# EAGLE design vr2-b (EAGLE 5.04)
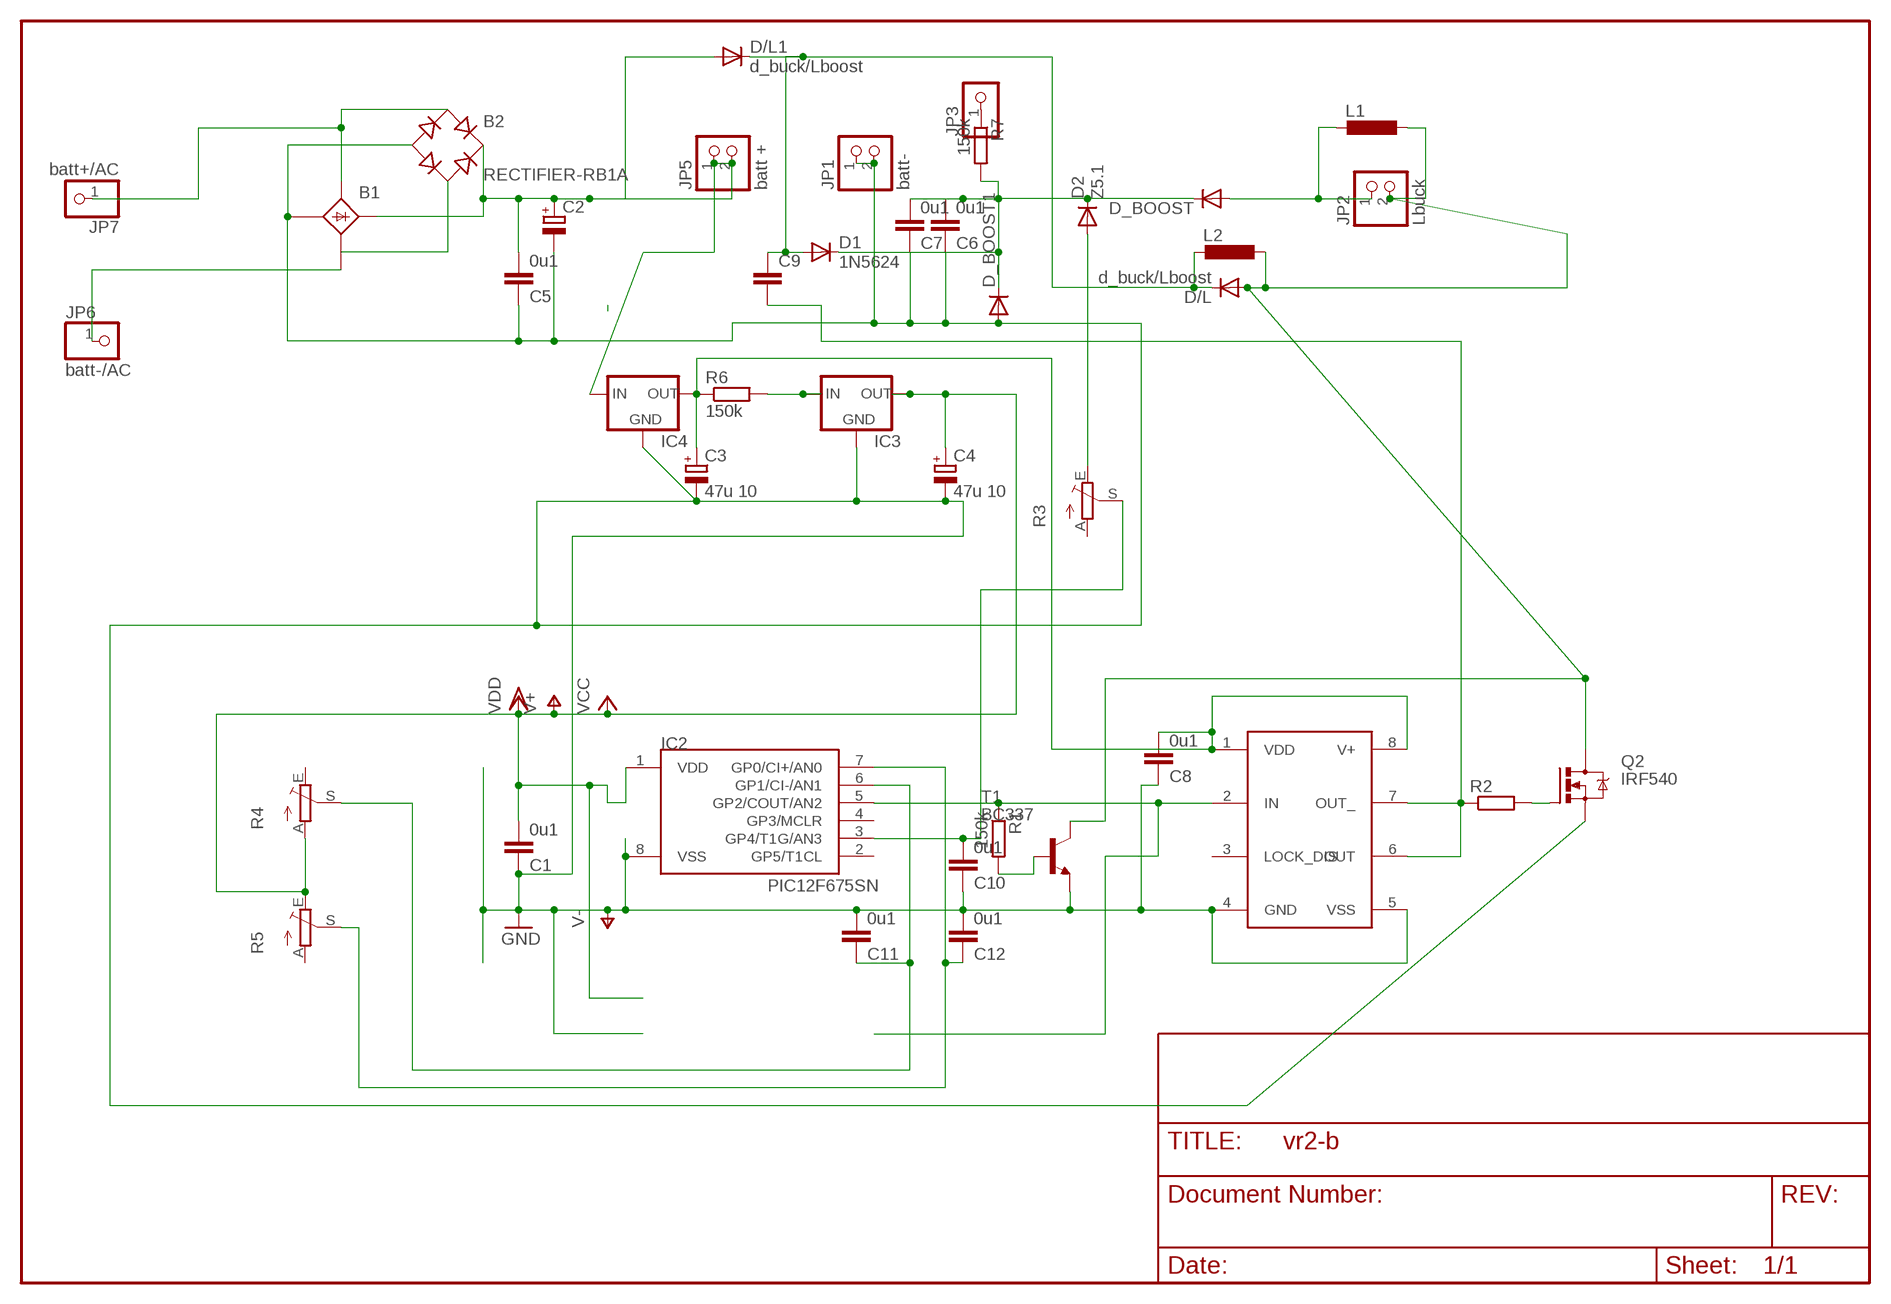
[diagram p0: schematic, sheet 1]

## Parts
B1  B25A-  [B25A-]
B2  RECTIFIER-RB1A  [RB1A]
C1  0u1  C-EUC1206  [C1206]
C2  CPOL-EUE7.5-18  [E7,5-18]
C3  47u 10  CPOL-EUE2,5-6E  [E2,5-6E]
C4  47u 10  CPOL-EUE2.5-6  [E2,5-6]
C5  0u1  C-EUC1206  [C1206]
C6  0u1  C-EUC1206  [C1206]
C7  0u1  C-EUC1206  [C1206]
C8  0u1  C-EUC1206  [C1206]
C9  C-EU050-024X044  [C050-024X044]
C10  0u1  C-EUC1206  [C1206]
C11  0u1  C-EUC1206  [C1206]
C12  0u1  C-EUC1206  [C1206]
D1  1N5624  [DO201-15]
D2  Z5.1  DIODE-D-2.5  [D-2.5]
D/L  d_buck/Lboost  DIODE-C1702-05  [C1702-05]
D/L1  d_buck/Lboost  DIODE-DO201-15  [DO201-15]
D_BOOST  DIODE-DO201-15  [DO201-15]
D_BOOST1  DIODE-DO201-15  [DO201-15]
IC1  TC4432X  [SO-08]
IC2  PIC12F675SN  [SO-08]
IC3  78LXX  [78LXX]
IC4  78LXX  [78LXX]
JP1  batt-  PINHD-1X2  [1X02]
JP2  Lbuck  PINHD-1X2  [1X02]
JP3  PINHD-1X1  [1X01]
JP5  batt +  PINHD-1X2  [1X02]
JP6  batt-/AC  PINHD-1X1  [1X01]
JP7  batt+/AC  PINHD-1X1  [1X01]
L1  DO3316P  [DO3316P]
L2  DO3316P  [DO3316P]
Q2  IRF540  [TO220BV]
R1  150k  R-EU_0207/12  [0207/12]
R2  R-EU_R1206  [R1206]
R3  TRIM_EU-CA6V  [CA6V]
R4  TRIM_EU-CA6V  [CA6V]
R5  TRIM_EU-CA6V  [CA6V]
R6  150k  R-EU_0204/7  [0204/7]
R7  150k  R-EU_0207/12  [0207/12]
T1  BC337  [TO92]

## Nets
LOAD: C6.2 C7.2 D1.C D2.C D_BOOST1.C D_BOOST.C R7.2
N$1: B1.+ B2.+ C2.+ C5.2 D/L1.A IC4.IN JP5.1 JP5.2
N$2: C9.1 D1.A D/L1.C D/L.C L2.1
N$3: B1.AC2-(AC2) JP6.1
N$4: C3.+ C8.2 IC1.1(VDD) IC1.8(V+) IC4.OUT R6.1
N$5: D_BOOST.A JP2.1 L1.1
N$6: R1.2 T1.2(B)
N$7: C9.2 IC1.6(OUT) IC1.7(OUT_) R2.1
N$8: B1.AC1 B2.AC1 JP7.1
N$9: D/L.A JP2.2 L1.2 L2.2 Q2.D T1.3(C)
N$11: B1.AC2 B2.AC2
N$12: C10.2 IC2.3(GP4/T1G/AN3) R3.S
N$13: C12.1 IC2.7(GP0/CI+/AN0) R5.S
N$14: IC1.2(IN) IC2.5(GP2/COUT/AN2) R1.1
N$15: C11.1 IC2.6(GP1/CI-/AN1) R4.S
N$16: D2.A R3.E
N$17: Q2.G R2.2
N$19: JP3.1 R7.1
N$20: IC3.IN R6.2
V+: C1.2 C4.+ IC2.1(VDD) IC3.OUT R4.A R5.E ; supply symbol labelled VCC, VDD
V-: B1.-1(-) B2.- C1.1 C2.- C3.- C4.- C5.1 C6.1 C7.1 C8.1 C10.1 C11.2 C12.2 D_BOOST1.A IC1.4(GND) IC1.5(VSS) IC2.8(VSS) IC3.GND IC4.GND JP1.1 JP1.2 Q2.S T1.1(E) ; supply symbol labelled GND
Unconnected: B1.+1(+) B1.- B1.AC1-(AC1) IC1.3(LOCK_DIS) IC2.2(GP5/T1CL) IC2.4(GP3/MCLR) R3.A R4.E R5.A

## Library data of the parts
B1 = rectifier:B25A-: RECTIFIER 25-A bridge
B2 = rectifier:RECTIFIER-: Rectifier
C1 C5-C8 C10-C12 = rcl:C-EU: CAPACITOR, European symbol
C2-C4 = rcl:CPOL-EU: POLARIZED CAPACITOR, European symbol
C9 = rcl-2:C-EU: CAPACITOR, European symbol
D1 = diode-1:1N5624: DIODE
D2 D/L D/L1 D_BOOST D_BOOST1 = diode:DIODE-: DIODE
IC1 = microchip:TC4432
IC2 = microchip-3:PIC12F6*: uPC nW 1k Program Flash memory 2x Timer Comparator 10b A/D converter/ 4xIN
IC3 IC4 = v-reg:78LXX: VOLTAGE REGULATOR
JP1 JP2 JP5 = pinhead:PINHD-1X2: PIN HEADER
JP3 JP6 JP7 = pinhead:PINHD-1X1: PIN HEADER
L1 L2 = inductor-coilcraft:DO3316P: COILCRAFT
Q2 = transistor-power:IRF540: HEXFET Power MOSFET
R1 R6 R7 = rcl:R-EU_: RESISTOR, European symbol
R2 = rcl-2:R-EU_: RESISTOR, European symbol
R3-R5 = pot:TRIM_EU-: POTENTIOMETER
T1 = transistor-neu-to92:BC337: NPN TRANSISTOR

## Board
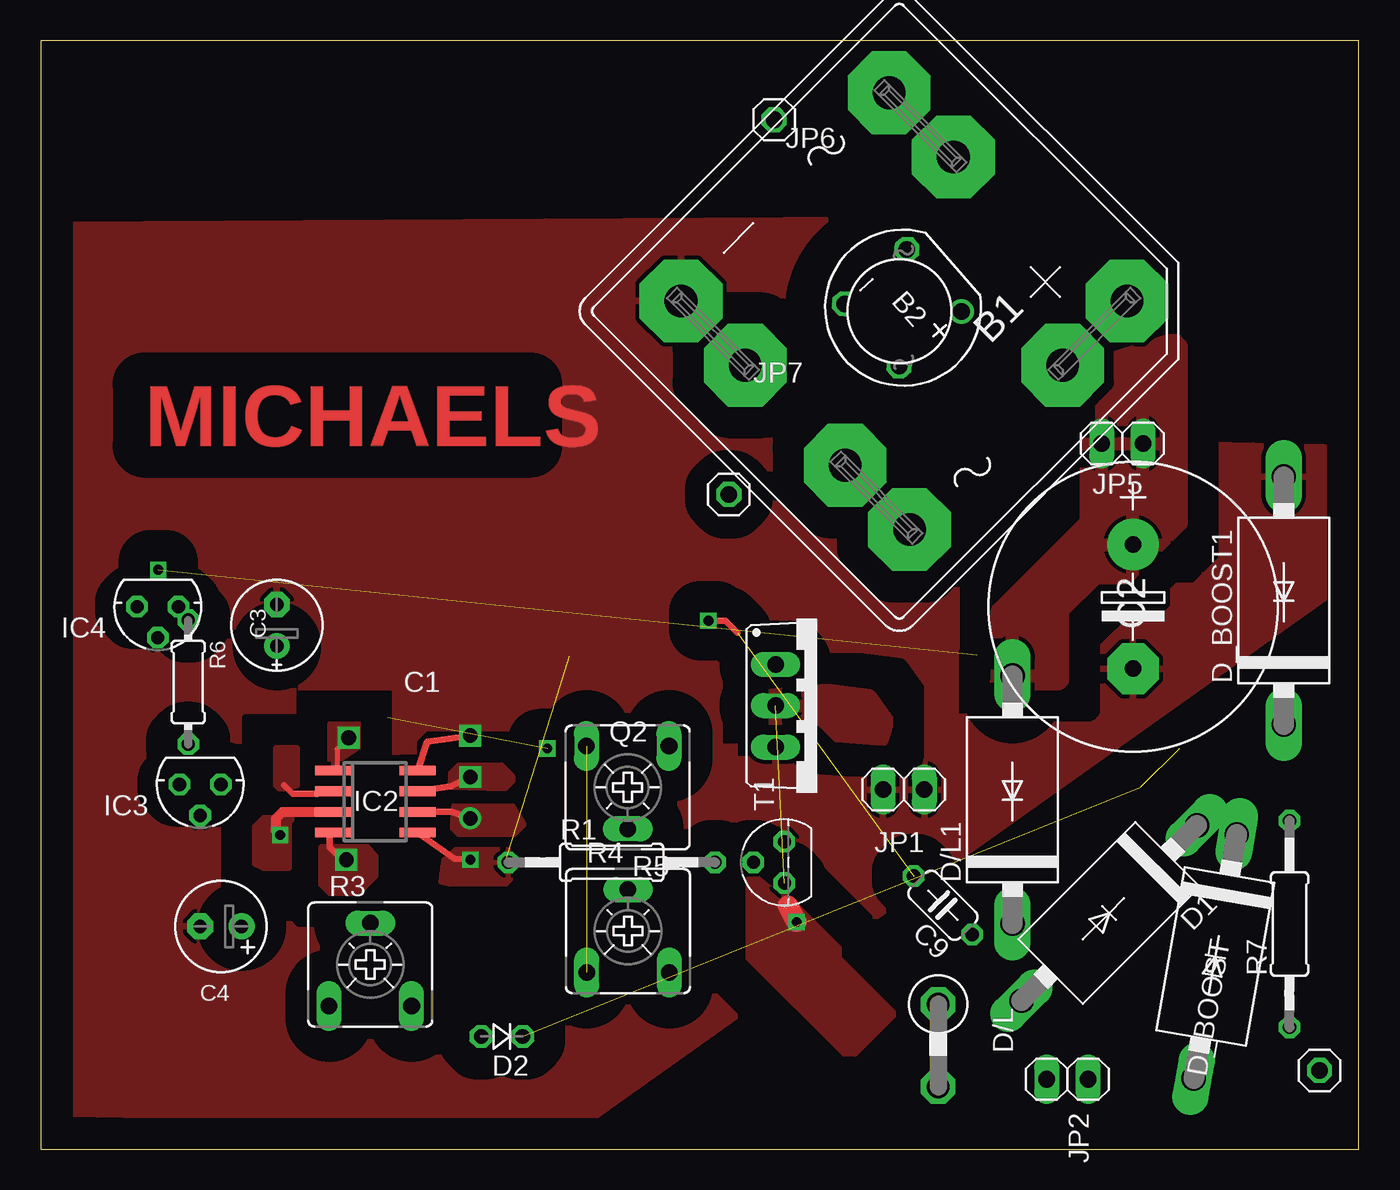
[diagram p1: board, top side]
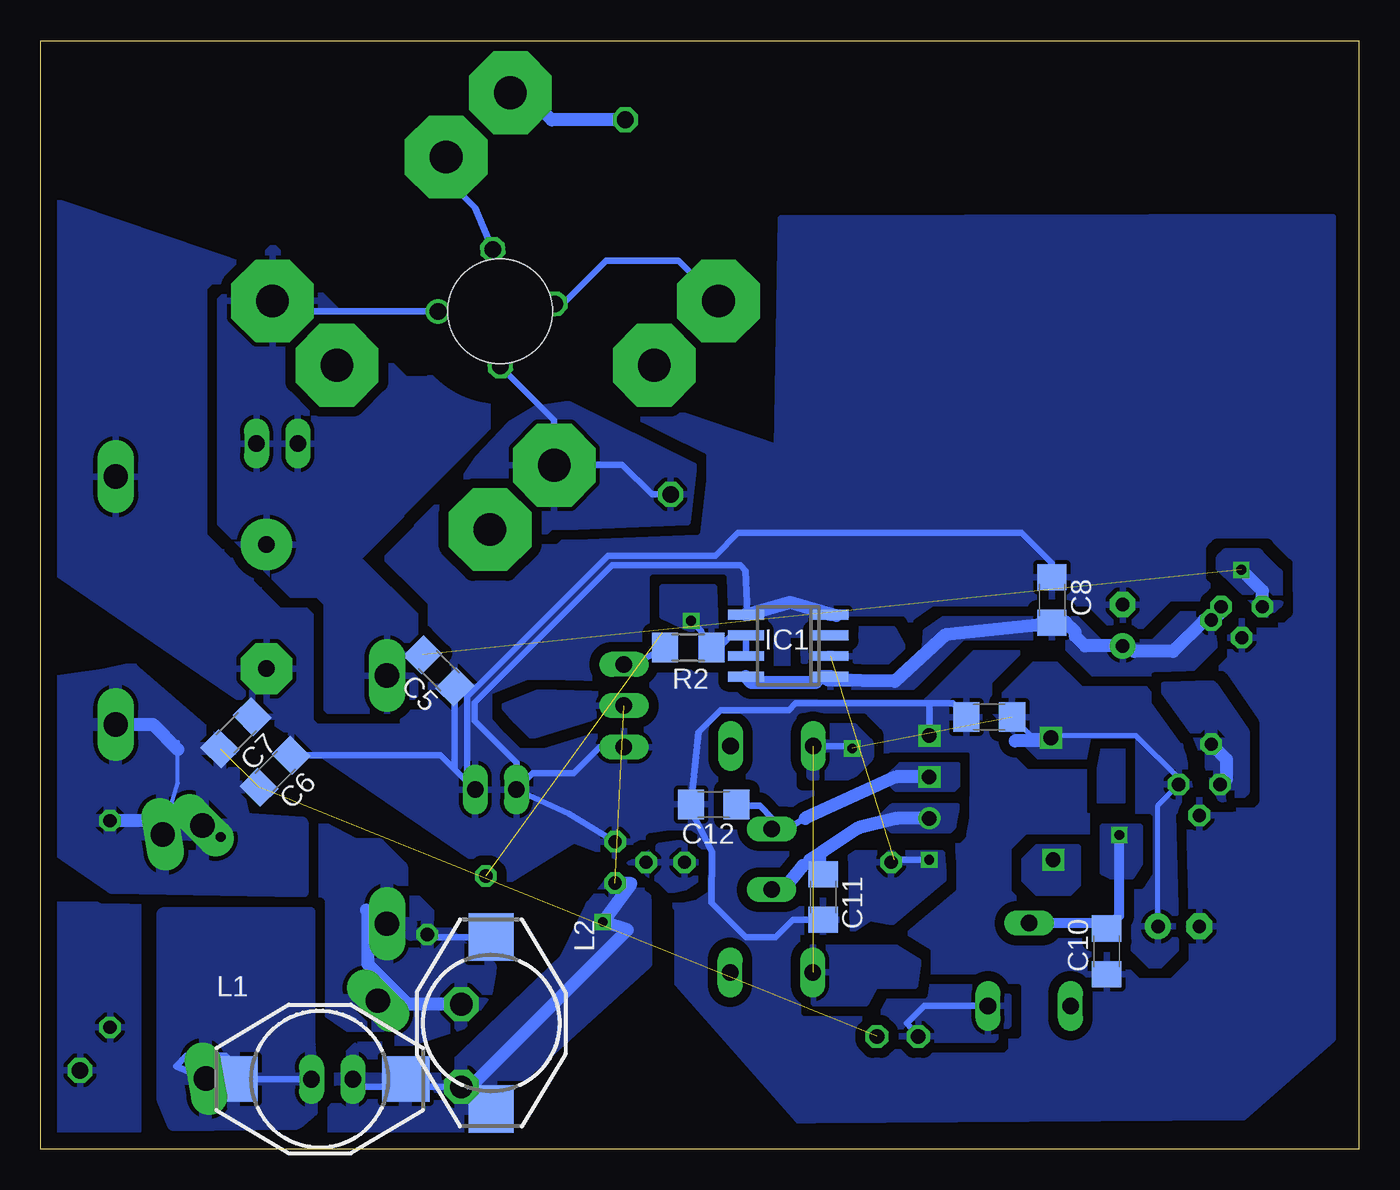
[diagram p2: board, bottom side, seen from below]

Size 81 x 68.09 mm. Coordinates in mm from the lower left corner, seen from the top.
Outline: 0,0 81,0 81,68.09 0,68.09 0,0
Copper layers (1*16): Top 0.035mm / dielectric 1.5mm / Bottom 0.035mm
Design rules "default": minimum track width 10mil, minimum drill 24mil, track to track 8mil, track to pad 8mil, pad to pad 8mil, via to via 8mil, smd to smd 8mil, copper to edge 40mil, drill to drill 8mil, minimum pad ring 10mil, minimum via ring 8mil, stop-mask expansion 4mil, vias tented up to drill 0mil, thermal gap 10mil

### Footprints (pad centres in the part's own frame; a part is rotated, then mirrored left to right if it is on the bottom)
B25A- = drill 2.007 pad 5.08 octagon: + -10.338,9.449; +1 -4.75,9.449; - 9.042,-4.343; -1 9.042,-9.931; AC1 9.042,4.343; AC1- 9.042,9.931; AC2 -9.042,-4.343; AC2- -9.042,-9.931 | hole 6.401: 0,0
RB1A = drill 1.016 round: + -2.54,2.54 | drill 1.016 octagon: - 2.54,-2.54; AC1 2.54,2.54; AC2 -2.54,-2.54
C1206 = smd 1.6 x 1.8: 1 -1.4,0; 2 1.4,0
E7,5-18 = drill 1.016 pad 3.15 round: + -3.81,0 | drill 1.016 pad 3.15 octagon: - 3.81,0
E2,5-6E = drill 0.813 pad 1.575 round: + -1.27,0 | drill 0.813 pad 1.575 octagon: - 1.27,0
E2,5-6 = drill 0.813 pad 1.6 round: + -1.27,0 | drill 0.813 pad 1.6 octagon: - 1.27,0
C050-024X044 = drill 0.813 octagon: 1 -2.54,0; 2 2.54,0
DO201-15 = drill 1.499 long: A 7.62,0; C -7.62,0
D-2.5 = drill 0.9 octagon: A 1.27,0; C -1.27,0
C1702-05 = drill 1.397 octagon: A 2.54,0; C -2.54,0
SO-08 = smd 0.6 x 2.2: 1 -1.905,-2.6; 2 -0.635,-2.6; 3 0.635,-2.6; 4 1.905,-2.6; 5 1.905,2.6; 6 0.635,2.6; 7 -0.635,2.6; 8 -1.905,2.6
78LXX = drill 0.813 octagon: GND 0,1.905; IN 1.27,0; OUT -1.27,0
1X02 = drill 1.016 long: 1 -1.27,0; 2 1.27,0
1X01 = drill 1.016 octagon: 1 0,0
DO3316P = smd 2.92 x 2.79: 1 -5.28,0; 2 5.28,0
TO220BV = drill 1.016 long: D 0,-2.54; G -2.54,-2.54; S 2.54,-2.54
0207/12 = drill 0.813 octagon: 1 -6.35,0; 2 6.35,0
R1206 = smd 1.6 x 1.803: 1 -1.422,0; 2 1.422,0
CA6V = drill 1.016 long: A -2.54,-2.54; E 2.54,-2.54; S 0,2.54
0204/7 = drill 0.813 octagon: 1 -3.81,0; 2 3.81,0
TO92 = drill 0.813 octagon: 1 1.27,0; 2 0,1.905; 3 -1.27,0

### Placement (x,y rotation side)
B1  52.76,51.47 225 top
B2  52.99,51.69 221.3 top
C1  22.7,26.54 0 bottom
C2  67.13,33.32 270 top
C3  14.51,32.18 90 top
C4  11.07,13.68 180 top
C5  56.54,29.38 135 bottom
C6  66.59,23.21 225 bottom
C7  68.99,25.58 225 bottom
C8  18.86,33.73 270 bottom
C9  55.44,14.98 135 top
C10  15.49,12.15 90 bottom
C11  32.92,15.49 270 bottom
C12  39.63,21.17 180 bottom
D1  65.66,14.5 225 top
D2  28.34,6.92 180 top
D/L  55.15,6.36 270 top
D/L1  59.72,21.46 90 top
D_BOOST  72.18,11.83 260 top
D_BOOST1  76.39,33.69 90 top
IC1  35.06,30.92 90 bottom
IC2  20.56,21.35 270 top
IC3  9.8,22.4 180 top
IC4  7.2,33.32 180 top
JP1  53.03,22.09 180 top
JP2  63.09,4.29 180 top
JP3  78.58,4.84 0 top
JP5  66.47,43.35 180 top
JP6  45.07,63.23 0 top
JP7  42.29,40.22 0 top
L1  63.85,4.31 0 bottom
L2  53.32,7.75 270 bottom
Q2  47.7,27.24 270 top
R1  35.09,17.61 0 top
R2  41.21,30.81 180 bottom
R3  20.25,11.34 0 top
R4  36.09,13.4 0 top
R5  36.07,22.22 180 top
R6  9.06,28.69 270 top
R7  76.74,13.83 90 top
T1  45.7,17.61 90 top

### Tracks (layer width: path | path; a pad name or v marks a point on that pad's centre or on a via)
LOAD  (via drill 0.6)  (2 unrouted)
  Bottom 0.254: 72.58,25.02 72.58,24.55 72.58,22.48 D_BOOST.C
  Bottom 0.406: 72.7,20.46 72.83,20.59 | 72.7,20.46 D_BOOST.C | v69.94,19.18 71.29,19.05 72.7,20.46
  Bottom 0.813: D_BOOST1.C 74.1,26.07 72.58,24.55 | D_BOOST.C 72.6,20.34 72.58,20.32 72.72,20.18 R7.2
  pour Bottom (isolate 0.61, rank 2): 68.51,20.29 64.94,20.04 64.93,15.84 76.62,16.07 81.04,19.1 81.04,28.59 77.09,29.13 75.4,29.51 69.44,24.38
N$1  (via drill 0.6)  (1 unrouted)
  Top 0.406: JP5.1 67.92,43.18
  Bottom 0.406: B2.+ 65.28,51.46 66.06,52.23 66.62,52.23 B1.+
  Bottom 0.813: IC4.IN 5.93,34.29 v7.22,35.59
  pour Bottom (isolate 0.61): 5.6,33.03 5.04,33.59 5.04,35.32 6.23,36.51 8.12,36.51 8.44,36.2 8.44,35.8
  pour Bottom (isolate 0.61, rank 2): 53.54,49 53.54,44.32 58.86,39 58.86,38.9 61.71,36.06 61.24,36.06 58,32.82 58,27.88 58.95,26.92 63.33,26.92 63.42,27.01 63.42,33.5 63.98,34.06 65.6,34.06 69.97,38.43 69.97,52.18 66.8,55.36 66.66,55.36 58.58,47.28 57.22,47.28 55.85,48.65 55.85,48.78 55.85,49.06 55.44,49.47
  pour Top (isolate 0.61): 69.62,49.81 70.08,49.35 70.08,38.39 66.76,35.08 64.83,35.08 62.79,33.03 62.79,28.79 62.56,28.56 58.68,28.56 58.8,28.68 58.8,33.13 64.26,38.6 64.26,48.09
N$2
  Bottom 0.406: L2.1 57.24,13.03 C9.1
  Bottom 0.813: D/L.C 58.42,8.9 60.88,11.37 60.88,14.57 60.99,14.68 D/L1.C
  pour Bottom (isolate 0.61, rank 3): 53.36,11.19 53.63,9.65 55,7.75 59.95,6.12 64.45,9.22 64.32,20.07 61.73,18.72 60.22,18.72 58.82,17.32 58.82,16.14 54.73,12.05
N$3
  Bottom 0.813: JP6.1 49.6,63.23 51.95,65.58 51.95,64.49 51.67,64.21 51.69,64.21 52.13,64.66 B1.AC2-
N$4
  Bottom 0.813: IC1.8 37.66,29 37.32,28.66 33.38,28.66 33.03,29.02 IC1.1 32.61,28.8 28.52,28.74 25.41,31.59 18.02,32.37 17.42,31.77 17.42,31.51 16.82,30.91 C3.+ 14.13,30.91 13.8,30.58 11.43,30.58 9.51,32.5 R6.1 8.99,32.44 8.47,32.96 IC4.OUT
  pour Bottom (isolate 0.61, rank 2): 9.15,32.87 10.89,32.87 12.63,31.13 15.88,31.13 17.31,32.55 25.5,32.59 26.62,31.81 26.72,29.86 29.33,29.34 33.51,29.39 33.51,28.28 33.16,28.11 28.5,28.11 27.5,28.31 27.12,28.66 24.34,31.45 18.17,31.45 17.85,31.13 17.85,30.72 16.35,29.22 10.5,29.22 8.84,30.89
N$5
  Bottom 0.406: JP2.1 68.21,4.29 69.64,5.73 72.04,5.73 72.67,5.11 D_BOOST.A
  pour Bottom (isolate 0.61): 64.31,4.23 64.5,6.5 64.5,14.5 73.5,14.45 73.5,3.07 72.84,1.51 65.27,1.6 64.27,2.45
N$6
  pour Bottom (isolate 0.61): 44.8,17.54 43.14,18.44 42.96,18.64 41.72,18.83 40.36,17.96 40.36,16.78 41.39,16.09 42.34,15.88 42.94,16.47
N$7  (via drill 0.6)  (1 unrouted)
  Top 0.406: v41.03,32.46 42.08,32.46 42.82,31.73
  Bottom 0.406: 37.82,30.29 37.87,30.24 | IC1.7 37.82,30.29 | 37.82,30.29 37.66,30.45 IC1.6 38.55,31.56 39.41,30.71 39.92,30.79 R2.1 39.98,30.94 40.42,31.85 v41.03,32.46
  pour Bottom: 40.32,30.59 39.53,32.03 39.63,34.53 42.78,34.53 42.78,32.74 40.32,31.56
N$8
  Bottom 0.406: JP7.1 43.44,40.22 45.27,42.05 49.48,42.05 | 49.48,42.05 50.3,42.05 | 49.48,42.05 B1.AC1 49.44,44.78 B2.AC1
  pour Bottom (isolate 0.61, rank 2): 50.61,45.49 48.56,45.8 40.84,41.99 41.26,38.52 48.03,38.24 49.63,38.24 52.38,35.64 54.98,35.2 56.88,37.11 56.11,39.52 54.12,42.46 52.16,44.55
N$9  (via drill 0.6)  (1 unrouted)
  Top 1.27: v46.45,13.96 45.91,14.96
  Bottom 0.406: 61.98,4.29 61.98,4.46 | 61.98,4.29 JP2.2 | D/L.A 61.98,3.82 61.98,4.29
  Bottom 0.813: D/L.A 54.58,3.82 44.94,13.46 v46.45,13.96 44.73,16.31 T1.3
  pour Bottom (isolate 0.813): 46.03,27.95 50.42,28.07 52.55,27.19 51.75,26.28 50.82,25.35 47.24,26.48 46.39,26.9
  pour Bottom (isolate 0.61, rank 2): 43.86,16.68 46.05,16.33 47.15,14.92 48.73,11.7 56.38,4.33 58.16,4.33 60.02,6.18 61.53,6.18 62.39,5.32 65.74,0.47 65.21,-0.06 56.51,-0.06 43.8,11.46
  pour Top: 45.3,15.61 45.79,15.61 49.03,12.37 49.03,11.76 52.44,8.36 52.44,8.24 50.07,5.88 49.36,5.88 43.53,11.71 43.53,16.59 43.76,16.81
  pour Top (isolate 0.61): 44.32,27.65 44.55,27.88 48.31,28.22 50.92,27.88 52.07,26.28 51.72,25.13 48.99,25.36 47.96,26.39 44.21,26.39
N$10  (via drill 0.9)
  Top 0.406: v18.78,17.78 18.53,17.78 17.76,18.54 17.76,19.3
  pour Bottom: 17.26,18.54 19.8,18.54 20.56,17.78 20.56,16.51 19.8,15.75 17.76,15.75 17.26,16.26
  pour Top: 17.26,18.54 17.26,16.26 17.76,15.75 19.54,15.75 19.8,16 20.56,16.76 20.56,18.03 20.05,18.54
N$11
  Bottom 0.406: B2.AC2 54.32,57.81 56.56,60.06 56.56,60.46 B1.AC2
N$12  (via drill 0.6)
  Top 0.61: IC2.3 14.86,20.71 14.46,20.32 14.46,19.56 v14.72,19.3
  Bottom 0.61: R3.S 15.82,13.88 C10.2 14.72,14.33 v14.72,19.3
  pour Top: 13.7,20.32 15.48,20.32 15.22,20.07 15.22,17.27 13.7,17.27 13.19,17.53 13.19,19.81
  pour Bottom (isolate 0.61): 15.73,19.81 15.73,17.02 15.22,16.76 13.95,16.76 13.45,17.53 13.45,19.81
N$13  (via drill 0.9)
  Top 0.406: IC2.7 25.22,22.28 v26.4,22.86
  Bottom 0.406: 34.02,20.32 34.92,19.81 R5.S 36.07,20.34 36.81,21.08 38.14,21.08 C12.1
  Bottom 0.813: v26.4,22.86 28.43,22.86 34.02,20.32
  pour Bottom (isolate 0.61): 24.62,23.62 28.18,23.62 28.94,22.86 28.94,22.61 28.43,22.1 24.88,22.1 24.62,22.35
  pour Top (isolate 0.61, rank 2): 25.2,22.2 25.2,23.1 25.7,23.6 28.3,23.6 29,22.9 29,22.6 28.5,22.1
N$14  (via drill 0.6)  (1 unrouted)
  Top 0.406: IC2.5 25.44,17.84 v26.4,17.78
  Bottom 0.406: v26.4,17.78 28.57,17.78 R1.1
  pour Bottom (isolate 0.61, rank 2): 25.63,18.19 31.2,18.2 31.09,13.47 30.04,14.19 28.69,13.93 25.5,16.61
  pour Bottom (isolate 0.61): 30.5,29.44 28.81,29.38 28.06,29.07 28.06,30.98 28.6,31.94 34.19,31.95 34.08,29.95 30.81,29.76
  pour Top (isolate 0.61): 24.76,17.78 24.56,16.44 25.1,16.3 28.6,16.3 29.7,17.4 29.7,18 29.3,18.4 25.5,18.4 25.1,18
N$15  (via drill 0.9)
  Top 0.406: IC2.6 25.24,20.71 v26.4,20.32
  Bottom 0.406: 35.65,15.84 35.28,16.09 R4.S | 33.73,17.77 34.17,17.44 | C11.1 32.91,18.23 32.96,18.27
  Bottom 0.813: 33.73,17.77 32.96,18.27 30.74,19.74 28.38,20.32 v26.4,20.32 | 34.17,17.44 35.28,16.09
  pour Bottom (isolate 0.61): 24.62,21.08 28.69,21.08 29.45,20.32 28.69,19.56 25.13,19.56 24.88,19.81
  pour Top (isolate 0.61, rank 2): 25.4,21.1 29,21.1 29.7,20 29.7,19.9 29.1,19.3 25.7,19.3 25.3,19.7
N$16
  Bottom 0.406: D2.A 27.77,7.72 26.69,8.8 R3.E
  pour Bottom (isolate 0.61, rank 2): 23.15,9.94 28.36,9.94 30.21,8.09 30.21,7.3 29.64,6.73 22.42,6.73 21.55,7.61 21.55,9.39 21.87,9.7
N$17
  Bottom 0.406: Q2.G 45.09,29.78 44.9,29.59 R2.2
N$18
  pour Bottom (isolate 0.61): 15.73,24.64 14.46,24.64 14.46,21.34 15.99,21.34 15.99,23.37
N$19
  pour Bottom (isolate 0.61, rank 3): 75,1.13 81.01,1.22 81.24,3.64 81.24,11.06 80,15 78,15 75,15.05
N$20
  Bottom 0.813: R6.2 9.06,24.87 8.12,23.93 8.12,22.75 8.53,22.34 IC3.IN
  pour Bottom (isolate 0.61): 9.89,25.59 11.9,28.33 9.06,28.42 7.1,25.58 7.1,22.02 7.41,21.7 8.37,21.7
N$88
  Top 0.406: 17,21.84 15.48,21.84 14.97,22.35
  pour Top: 14.72,22.1 14.46,22.35 14.46,24.64 15.73,24.64 15.73,22.35
V+  (via drill 0.6, 0.9)  (2 unrouted)
  Top 0.305: 18.21,23.43 18.21,24.57 v18.92,25.27
  Top 0.406: 18.21,23.43 IC2.1
  Bottom 0.305: C1.2 20.16,25.4 18.78,25.4 18.91,25.27 v18.92,25.27 18.79,25.4 13.7,25.4 11.07,22.77 IC3.OUT 12.34,21.13 C4.+
  Bottom 0.406: 19.03,25.39 v18.92,25.27 19.11,25.08 | R5.E 31.28,24.76 v31.14,24.61
  Bottom 0.813: 19.11,25.08 21.13,25.08
  pour Bottom (isolate 0.61): 33.59,25.81 31.09,25.81 30.2,24.92 30.2,24.08 31.25,23.03 33.59,23.03 33.98,23.42
  pour Bottom (isolate 0.61, rank 3): 11.24,13.77 11.24,12.24 12.19,11.29 12.85,11.29 14.46,12.9 14.27,24.13 19.68,24.13 22.64,27.09 22.63,27.09 19.97,29.74 17.51,29.74 13.74,29.02 12.47,27.43 10.89,24.68 10.28,21.76 11.43,20.61
  pour Bottom (isolate 0.61): 28.41,12.36 33.94,12.36 33.94,12.12 33.47,12.12 33.47,8.95 30.3,8.95 29.71,10.05 27.26,10.05 27.05,11.53
  pour Top (isolate 0.61): 18.02,23.62 17.76,23.62 17.76,26.16 19.54,26.16 19.54,24.64
V-  (via drill 0.9)
  Top 0.406: IC2.8 23.75,25.03 v26.4,25.4
  Bottom 0.406: B2.- 48.9,51.92 46.26,54.56 41.8,54.56 B1.-1 | C6.1 56.42,24.2 54.82,22.6 | C5.1 55.55,23.33 54.82,22.6 | 54.82,22.6 JP1.1 | JP1.2 51.76,23.75 54.34,26.33 54.34,27.41 45.88,35.87 38.01,35.87 37.68,35.53 37.58,32.91 IC1.5 | JP1.2 51.45,21.78 | T1.1 48.52,20.6 JP1.2 | Q2.S 46.64,24.7 48.26,23.09 50.76,23.09 JP1.2 | C8.1 18.86,35.98 20.74,37.86 38.15,37.86 39.54,36.46 46.15,36.46 54.81,27.8 54.81,22.61 54.82,22.6 | 26.4,27.39 34.6,27.39 35.02,26.98 39.23,26.98 40.59,25.61 C12.2 41.31,21.06 40.76,20.26 39.75,18.27 39.79,15.13 37.66,13.01 35.85,13.01 34.76,14.09 C11.2 | 26.4,27.39 24.95,27.39 C1.1 | 26.4,27.39 v26.4,25.4
  Bottom 0.813: 34.96,33.59 IC1.4 | IC1.5 34.96,33.59 | 34.96,33.59 32.11,32.78
  pour Bottom (isolate 0.61, rank 4): 1.6,57.29 1.6,6.79 7.11,1.97 33.44,1.78 34.45,1.78 41.87,10.15 41.87,14.69 43.66,17.21 48.23,18.97 52.35,16.43 80.77,35.9 80.77,44.59 81.1,58.56 35.75,43.12 35.51,57.18
  pour Top (isolate 1.93, rank 3): 1.46,56.78 55.48,57.12 49.34,44.32 61.64,36.68 70.3,43.29 81.71,43.07 80.79,35.19 33.49,1.6 1.79,2.17

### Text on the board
Top: MICHAELS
